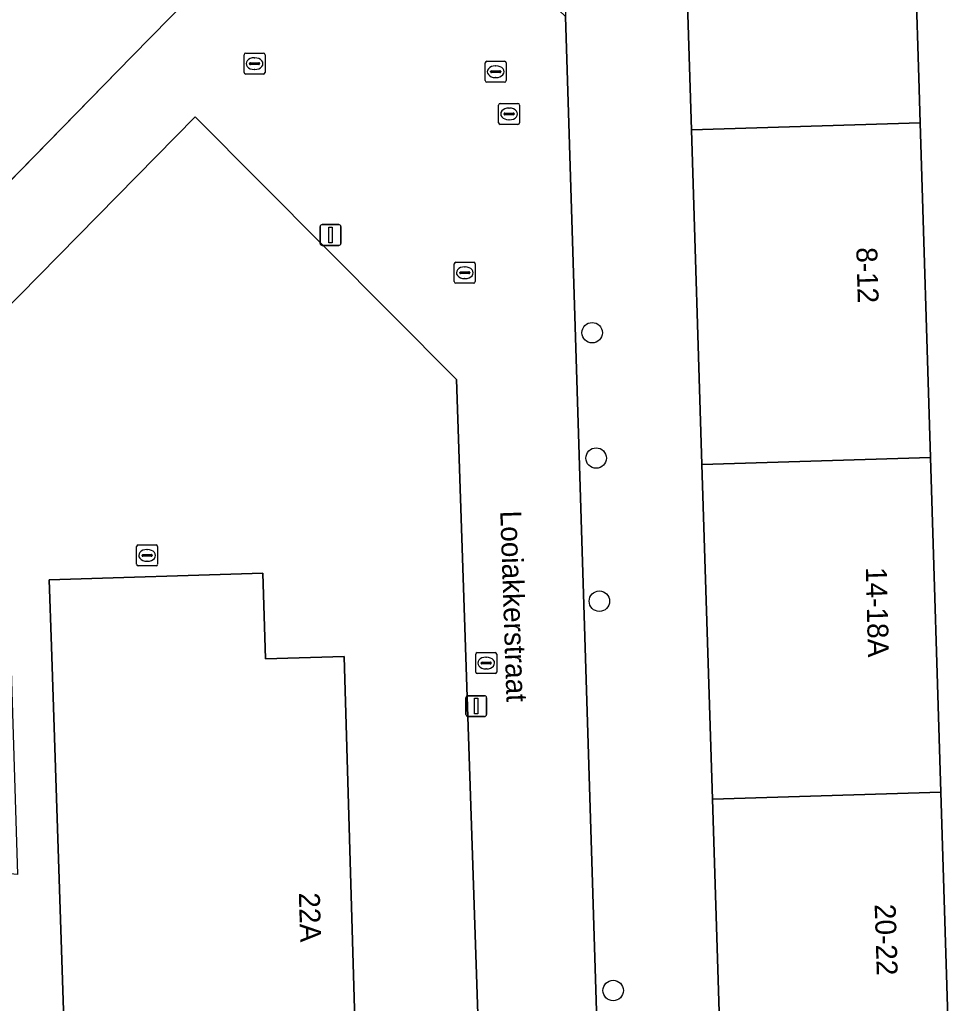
# Model space of a CAD drawing. Extents: x 161402 to 161933, y 381647 to 382315.
# Drawn here: x 161864.17 to 161908.71, y 382100.29 to 382147.3 of the extents above; entities that cross this region are included whole.
import ezdxf

# ---------------------------------------------------------------- set-up
doc = ezdxf.new("R2010")
doc.units = 0
for name, color, linetype in [('IMGEO_Boom', 7, 'Continuous'), ('IMGEO_Erf', 7, 'Continuous'), ('IMGEO_Kolk', 7, 'Continuous'), ('IMGEO_Lichtmast', 7, 'Continuous'), ('IMGEO_Muur', 7, 'Continuous'), ('IMGEO_Openbare_ruimte_label', 7, 'Continuous'), ('IMGEO_Pand', 7, 'Continuous'), ('IMGEO_Pand_nummerreeks', 7, 'Continuous'), ('IMGEO_Parkeervlak_open', 7, 'Continuous'), ('IMGEO_Rijbaan_lokaal_open', 7, 'Continuous'), ('IMGEO_Rioolput', 7, 'Continuous'), ('IMGEO_Voetpad_open', 7, 'Continuous')]:
    doc.layers.add(name, color=color, linetype=linetype)

msp = doc.modelspace()

# ---------------------------------------------------------------- linework, layer by layer
at = {"layer": 'IMGEO_Boom'}
for centre in [(161891.541, 382132.339), (161891.73, 382126.349), (161891.886, 382119.508), (161892.545, 382100.904)]:
    msp.add_circle(centre, 0.489, dxfattribs=at)
at = {"layer": 'IMGEO_Erf'}
msp.add_lwpolyline([(161859.667, 382135.458), (161869.551, 382145.549), (161877.656, 382153.823)], dxfattribs=at)
for points in [[(161885.051, 382130.105), (161872.557, 382142.66), (161863.229, 382133.182), (161864.069, 382106.453), (161861.265, 382106.705), (161849.74, 382095.198), (161850.155, 382094.961), (161849.637, 382091.837), (161856.605, 382090.577), (161856.514, 382090.075), (161857.282, 382089.936), (161857.022, 382088.5), (161864.705, 382087.108), (161864.747, 382086.071), (161881.604, 382083.709), (161886.502, 382086.978)], [(161875.799, 382120.848), (161875.926, 382116.75), (161879.684, 382116.866), (161880.342, 382094.587), (161881.463, 382094.624), (161881.653, 382088.841), (161866.197, 382088.354), (161866.014, 382094.144), (161866.456, 382094.154), (161865.684, 382117.343), (161865.575, 382120.533)]]:
    msp.add_lwpolyline(points, close=True, dxfattribs=at)
at = {"layer": 'IMGEO_Kolk'}
for p, q in [((161874.9, 382144.77), (161874.9, 382145.622)), ((161874.975, 382145.696), (161875.827, 382145.696)), ((161875.388, 382145.476), (161875.413, 382145.476)), ((161875.901, 382145.622), (161875.901, 382144.77)), ((161875.159, 382145.19), (161875.159, 382145.202)), ((161875.597, 382145.153), (161875.199, 382145.153)), ((161875.202, 382145.239), (161875.6, 382145.239)), ((161875.411, 382144.916), (161875.386, 382144.916)), ((161875.643, 382145.202), (161875.643, 382145.19)), ((161886.428, 382144.384), (161886.428, 382145.236)), ((161886.503, 382145.31), (161887.355, 382145.31)), ((161886.916, 382145.09), (161886.941, 382145.09)), ((161887.429, 382145.236), (161887.429, 382144.384)), ((161875.827, 382144.696), (161874.975, 382144.696)), ((161886.687, 382144.804), (161886.687, 382144.816)), ((161887.125, 382144.767), (161886.727, 382144.767)), ((161886.73, 382144.853), (161887.128, 382144.853)), ((161886.939, 382144.53), (161886.914, 382144.53)), ((161887.171, 382144.816), (161887.171, 382144.804)), ((161887.355, 382144.31), (161886.503, 382144.31)), ((161884.95, 382134.779), (161884.95, 382135.631)), ((161885.025, 382135.705), (161885.877, 382135.705)), ((161885.951, 382135.631), (161885.951, 382134.779)), ((161885.209, 382135.199), (161885.209, 382135.211)), ((161885.647, 382135.162), (161885.249, 382135.162)), ((161885.252, 382135.248), (161885.65, 382135.248)), ((161885.438, 382135.485), (161885.463, 382135.485)), ((161885.693, 382135.211), (161885.693, 382135.199)), ((161885.877, 382134.705), (161885.025, 382134.705)), ((161885.461, 382134.925), (161885.436, 382134.925)), ((161869.761, 382121.271), (161869.761, 382122.123)), ((161869.836, 382122.197), (161870.688, 382122.197)), ((161870.249, 382121.977), (161870.274, 382121.977)), ((161870.762, 382122.123), (161870.762, 382121.271)), ((161870.02, 382121.691), (161870.02, 382121.703)), ((161870.458, 382121.654), (161870.06, 382121.654)), ((161870.063, 382121.74), (161870.461, 382121.74)), ((161870.272, 382121.417), (161870.247, 382121.417)), ((161870.504, 382121.703), (161870.504, 382121.691)), ((161870.688, 382121.197), (161869.836, 382121.197)), ((161885.975, 382116.126), (161885.975, 382116.978)), ((161886.05, 382117.052), (161886.902, 382117.052)), ((161886.463, 382116.832), (161886.488, 382116.832)), ((161886.976, 382116.978), (161886.976, 382116.126)), ((161886.234, 382116.546), (161886.234, 382116.558)), ((161886.672, 382116.509), (161886.274, 382116.509)), ((161886.277, 382116.595), (161886.675, 382116.595)), ((161886.486, 382116.272), (161886.461, 382116.272)), ((161886.718, 382116.558), (161886.718, 382116.546)), ((161886.902, 382116.052), (161886.05, 382116.052))]:
    msp.add_line(p, q, dxfattribs=at)
for points in [[(161874.9, 382144.77), (161874.9, 382145.622)], [(161874.975, 382145.696), (161875.827, 382145.696)], [(161875.901, 382145.622), (161875.901, 382144.77)], [(161886.428, 382144.384), (161886.428, 382145.236)], [(161886.503, 382145.31), (161887.355, 382145.31)], [(161887.429, 382145.236), (161887.429, 382144.384)], [(161875.827, 382144.696), (161874.975, 382144.696)], [(161887.355, 382144.31), (161886.503, 382144.31)], [(161884.95, 382134.779), (161884.95, 382135.631)], [(161885.025, 382135.705), (161885.877, 382135.705)], [(161885.951, 382135.631), (161885.951, 382134.779)], [(161885.877, 382134.705), (161885.025, 382134.705)], [(161869.761, 382121.271), (161869.761, 382122.123)], [(161869.836, 382122.197), (161870.688, 382122.197)], [(161870.762, 382122.123), (161870.762, 382121.271)], [(161870.688, 382121.197), (161869.836, 382121.197)], [(161885.975, 382116.126), (161885.975, 382116.978)], [(161886.05, 382117.052), (161886.902, 382117.052)], [(161886.976, 382116.978), (161886.976, 382116.126)], [(161886.902, 382116.052), (161886.05, 382116.052)]]:
    msp.add_lwpolyline(points, dxfattribs=at)
for centre, radius, start, end in [((161874.977, 382145.62), 0.0765, 91.552, 178.448), ((161874.977, 382145.62), 0.0765, 91.552, 178.448), ((161875.825, 382145.62), 0.0765, 1.552, 88.448), ((161875.825, 382145.62), 0.0765, 1.552, 88.448), ((161875.199, 382145.199), 0.0403, 85.8775, 175.7526), ((161875.196, 382145.189), 0.0366, 178.938, 274.7102), ((161875.6, 382145.196), 0.043, 264.8664, 352.4533), ((161875.604, 382145.201), 0.0386, 1.7309, 96.639), ((161886.505, 382145.234), 0.0765, 91.552, 178.448), ((161886.505, 382145.234), 0.0765, 91.552, 178.448), ((161887.353, 382145.234), 0.0765, 1.552, 88.448), ((161887.353, 382145.234), 0.0765, 1.552, 88.448), ((161874.977, 382144.772), 0.0765, 181.552, 268.448), ((161874.977, 382144.772), 0.0765, 181.552, 268.448), ((161875.825, 382144.772), 0.0765, 271.552, 358.448), ((161875.825, 382144.772), 0.0765, 271.552, 358.448), ((161886.727, 382144.813), 0.0403, 85.8775, 175.7526), ((161886.724, 382144.803), 0.0366, 178.938, 274.7102), ((161887.128, 382144.81), 0.043, 264.8664, 352.4533), ((161887.132, 382144.815), 0.0386, 1.7309, 96.639), ((161886.505, 382144.386), 0.0765, 181.552, 268.448), ((161886.505, 382144.386), 0.0765, 181.552, 268.448), ((161887.353, 382144.386), 0.0765, 271.552, 358.448), ((161887.353, 382144.386), 0.0765, 271.552, 358.448), ((161885.027, 382135.629), 0.0765, 91.552, 178.448), ((161885.027, 382135.629), 0.0765, 91.552, 178.448), ((161885.875, 382135.629), 0.0765, 1.552, 88.448), ((161885.875, 382135.629), 0.0765, 1.552, 88.448), ((161885.249, 382135.208), 0.0403, 85.8775, 175.7526), ((161885.246, 382135.198), 0.0366, 178.938, 274.7102), ((161885.65, 382135.205), 0.043, 264.8664, 352.4533), ((161885.654, 382135.21), 0.0386, 1.7309, 96.639), ((161885.027, 382134.781), 0.0765, 181.552, 268.448), ((161885.027, 382134.781), 0.0765, 181.552, 268.448), ((161885.875, 382134.781), 0.0765, 271.552, 358.448), ((161885.875, 382134.781), 0.0765, 271.552, 358.448), ((161869.838, 382122.121), 0.0765, 91.552, 178.448), ((161869.838, 382122.121), 0.0765, 91.552, 178.448), ((161870.686, 382122.121), 0.0765, 1.552, 88.448), ((161870.686, 382122.121), 0.0765, 1.552, 88.448), ((161870.06, 382121.7), 0.0403, 85.8775, 175.7526), ((161870.057, 382121.69), 0.0366, 178.938, 274.7102), ((161870.461, 382121.697), 0.043, 264.8664, 352.4533), ((161870.465, 382121.702), 0.0386, 1.7309, 96.639), ((161869.838, 382121.273), 0.0765, 181.552, 268.448), ((161869.838, 382121.273), 0.0765, 181.552, 268.448), ((161870.686, 382121.273), 0.0765, 271.552, 358.448), ((161870.686, 382121.273), 0.0765, 271.552, 358.448), ((161886.052, 382116.976), 0.0765, 91.552, 178.448), ((161886.052, 382116.976), 0.0765, 91.552, 178.448), ((161886.9, 382116.976), 0.0765, 1.552, 88.448), ((161886.9, 382116.976), 0.0765, 1.552, 88.448), ((161886.274, 382116.555), 0.0403, 85.8775, 175.7526), ((161886.271, 382116.545), 0.0366, 178.938, 274.7102), ((161886.675, 382116.552), 0.043, 264.8664, 352.4533), ((161886.679, 382116.557), 0.0386, 1.7309, 96.639), ((161886.052, 382116.128), 0.0765, 181.552, 268.448), ((161886.052, 382116.128), 0.0765, 181.552, 268.448), ((161886.9, 382116.128), 0.0765, 271.552, 358.448), ((161886.9, 382116.128), 0.0765, 271.552, 358.448)]:
    msp.add_arc(centre, radius, start, end, dxfattribs=at)
for centre, major_axis, ratio, start_param, end_param in [((161875.387, 382145.196), (-0.387, 0.002), 0.722429, 4.712389, 7.853982), ((161875.412, 382145.196), (-0.39, 0.002), 0.717154, 1.570796, 4.712389), ((161886.915, 382144.81), (-0.387, 0.002), 0.722429, 4.712389, 7.853982), ((161886.94, 382144.81), (-0.39, 0.002), 0.717154, 1.570796, 4.712389), ((161885.437, 382135.205), (-0.387, 0.002), 0.722429, 4.712389, 7.853982), ((161885.462, 382135.205), (-0.39, 0.002), 0.717154, 1.570796, 4.712389), ((161870.248, 382121.697), (-0.387, 0.002), 0.722429, 4.712389, 7.853982), ((161870.273, 382121.697), (-0.39, 0.002), 0.717154, 1.570796, 4.712389), ((161886.462, 382116.552), (-0.387, 0.002), 0.722429, 4.712389, 7.853982), ((161886.487, 382116.552), (-0.39, 0.002), 0.717154, 1.570796, 4.712389)]:
    msp.add_ellipse(centre, major_axis=major_axis, ratio=ratio, start_param=start_param, end_param=end_param, dxfattribs=at)
at = {"layer": 'IMGEO_Lichtmast'}
for p, q in [((161878.536, 382136.609), (161878.536, 382137.409)), ((161878.536, 382137.409), (161878.536, 382136.609)), ((161878.636, 382137.509), (161879.426, 382137.509)), ((161879.426, 382137.509), (161878.636, 382137.509)), ((161879.526, 382137.409), (161879.526, 382136.609)), ((161879.526, 382136.609), (161879.526, 382137.409)), ((161879.426, 382136.509), (161878.636, 382136.509)), ((161878.636, 382136.509), (161879.426, 382136.509)), ((161885.502, 382114.095), (161885.502, 382114.895)), ((161885.502, 382114.895), (161885.502, 382114.095)), ((161885.602, 382114.995), (161886.392, 382114.995)), ((161886.392, 382114.995), (161885.602, 382114.995)), ((161886.492, 382114.895), (161886.492, 382114.095)), ((161886.492, 382114.095), (161886.492, 382114.895)), ((161886.392, 382113.995), (161885.602, 382113.995)), ((161885.602, 382113.995), (161886.392, 382113.995))]:
    msp.add_line(p, q, dxfattribs=at)
for points in [[(161878.956, 382137.384), (161879.106, 382137.384), (161879.106, 382136.634), (161878.956, 382136.634), (161878.956, 382137.384)], [(161885.922, 382114.87), (161886.072, 382114.87), (161886.072, 382114.12), (161885.922, 382114.12), (161885.922, 382114.87)]]:
    msp.add_lwpolyline(points, dxfattribs=at)
for centre, start, end in [((161878.636, 382137.409), 90, 180), ((161878.636, 382137.409), 90, 180), ((161879.426, 382137.409), 0, 90), ((161879.426, 382137.409), 360, 90), ((161878.636, 382136.609), 180, 270), ((161878.636, 382136.609), 180, 270), ((161879.426, 382136.609), 270, 0), ((161879.426, 382136.609), 270, 0), ((161885.602, 382114.895), 90, 180), ((161885.602, 382114.895), 90, 180), ((161886.392, 382114.895), 0, 90), ((161886.392, 382114.895), 360, 90), ((161885.602, 382114.095), 180, 270), ((161885.602, 382114.095), 180, 270), ((161886.392, 382114.095), 270, 0), ((161886.392, 382114.095), 270, 0)]:
    msp.add_arc(centre, 0.1, start, end, dxfattribs=at)
at = {"layer": 'IMGEO_Muur'}
for points in [[(161877.656, 382153.823), (161869.551, 382145.549)], [(161869.551, 382145.549), (161853.957, 382129.629)]]:
    msp.add_lwpolyline(points, dxfattribs=at)
at = {"layer": 'IMGEO_Pand'}
for points in [[(161896.284, 382142.031), (161907.227, 382142.376), (161907.16, 382144.524), (161906.736, 382158.205), (161906.731, 382158.368), (161895.524, 382158.015), (161895.537, 382157.595), (161895.793, 382157.603)], [(161896.788, 382126.039), (161907.722, 382126.383), (161907.227, 382142.376), (161896.284, 382142.031)], [(161896.788, 382126.039), (161897.292, 382110.047), (161908.217, 382110.391), (161907.722, 382126.383)], [(161879.684, 382116.866), (161875.926, 382116.75), (161875.799, 382120.848), (161865.575, 382120.533), (161865.684, 382117.343), (161866.456, 382094.154), (161866.014, 382094.144), (161866.197, 382088.354), (161881.653, 382088.841), (161881.463, 382094.624), (161880.342, 382094.587)], [(161908.217, 382110.391), (161897.292, 382110.047), (161897.788, 382094.302), (161897.528, 382094.294), (161897.538, 382093.965), (161908.487, 382094.311), (161908.715, 382094.318), (161908.71, 382094.477)]]:
    msp.add_lwpolyline(points, close=True, dxfattribs=at)
at = {"layer": 'IMGEO_Parkeervlak_open'}
msp.add_lwpolyline([(161893.381, 382093.835), (161897.538, 382093.965), (161897.528, 382094.294), (161897.788, 382094.302), (161897.292, 382110.047), (161896.788, 382126.039), (161896.284, 382142.031), (161895.793, 382157.603), (161895.537, 382157.595), (161895.524, 382158.015), (161889.95, 382157.839), (161890.273, 382147.456), (161891.937, 382093.79)], close=True, dxfattribs=at)
at = {"layer": 'IMGEO_Rijbaan_lokaal_open'}
for points in [[(161891.943, 382093.602), (161891.937, 382093.79), (161890.273, 382147.456), (161880.501, 382156.737), (161877.656, 382153.823), (161869.551, 382145.549), (161859.667, 382135.458), (161860.18, 382134.346)], [(161861.825, 382133.473), (161863.229, 382133.182), (161872.557, 382142.66), (161885.051, 382130.105), (161886.502, 382086.978), (161881.604, 382083.709), (161880.846, 382079.728), (161880.941, 382079.709), (161879.984, 382074.802)]]:
    msp.add_lwpolyline(points, dxfattribs=at)
at = {"layer": 'IMGEO_Rioolput'}
for p, q in [((161887.068, 382142.368), (161887.068, 382143.22)), ((161887.143, 382143.294), (161887.995, 382143.294)), ((161887.556, 382143.074), (161887.581, 382143.074)), ((161888.069, 382143.22), (161888.069, 382142.368)), ((161887.327, 382142.788), (161887.327, 382142.8)), ((161887.765, 382142.751), (161887.367, 382142.751)), ((161887.37, 382142.837), (161887.768, 382142.837)), ((161887.811, 382142.8), (161887.811, 382142.788)), ((161887.995, 382142.294), (161887.143, 382142.294)), ((161887.579, 382142.514), (161887.554, 382142.514))]:
    msp.add_line(p, q, dxfattribs=at)
for points in [[(161887.068, 382142.368), (161887.068, 382143.22)], [(161887.143, 382143.294), (161887.995, 382143.294)], [(161888.069, 382143.22), (161888.069, 382142.368)], [(161887.995, 382142.294), (161887.143, 382142.294)]]:
    msp.add_lwpolyline(points, dxfattribs=at)
for centre, radius, start, end in [((161887.145, 382143.218), 0.0765, 91.552, 178.448), ((161887.145, 382143.218), 0.0765, 91.552, 178.448), ((161887.993, 382143.218), 0.0765, 1.552, 88.448), ((161887.993, 382143.218), 0.0765, 1.552, 88.448), ((161887.367, 382142.797), 0.0403, 85.8775, 175.7526), ((161887.364, 382142.787), 0.0366, 178.938, 274.7102), ((161887.768, 382142.794), 0.043, 264.8664, 352.4533), ((161887.772, 382142.799), 0.0386, 1.7309, 96.639), ((161887.145, 382142.37), 0.0765, 181.552, 268.448), ((161887.145, 382142.37), 0.0765, 181.552, 268.448), ((161887.993, 382142.37), 0.0765, 271.552, 358.448), ((161887.993, 382142.37), 0.0765, 271.552, 358.448)]:
    msp.add_arc(centre, radius, start, end, dxfattribs=at)
for centre, major_axis, ratio, start_param, end_param in [((161887.555, 382142.794), (-0.387, 0.002), 0.722429, 4.712389, 7.853982), ((161887.58, 382142.794), (-0.39, 0.002), 0.717154, 1.570796, 4.712389)]:
    msp.add_ellipse(centre, major_axis=major_axis, ratio=ratio, start_param=start_param, end_param=end_param, dxfattribs=at)
at = {"layer": 'IMGEO_Voetpad_open'}
msp.add_lwpolyline([(161905.401, 382161.971), (161905.864, 382159.898), (161906.731, 382158.368), (161906.736, 382158.205), (161907.16, 382144.524), (161907.227, 382142.376), (161907.722, 382126.383), (161908.217, 382110.391), (161908.71, 382094.477), (161908.715, 382094.318), (161908.487, 382094.311), (161908.372, 382091.621), (161908.19, 382087.143), (161908.04, 382081.166), (161907.929, 382076.752), (161907.56, 382076.762), (161907.356, 382074.185)], dxfattribs=at)

# ---------------------------------------------------------------- texts
at = {"layer": 'IMGEO_Openbare_ruimte_label'}
msp.add_text('Looiakkerstraat', height=1, rotation=271.892, dxfattribs=at).set_placement((161887.146, 382123.821))
at = {"layer": 'IMGEO_Pand_nummerreeks'}
for s, rotation, p in [('8-12', 271.6523, (161904.168, 382136.411)), ('14-18A', 271.4755, (161904.624, 382121.129)), ('22A', 271.69, (161877.516, 382105.578)), ('20-22', 271.7989, (161905.047, 382105.027))]:
    msp.add_text(s, height=1, rotation=rotation, dxfattribs=at).set_placement(p)

doc.saveas('drawing.dxf')
